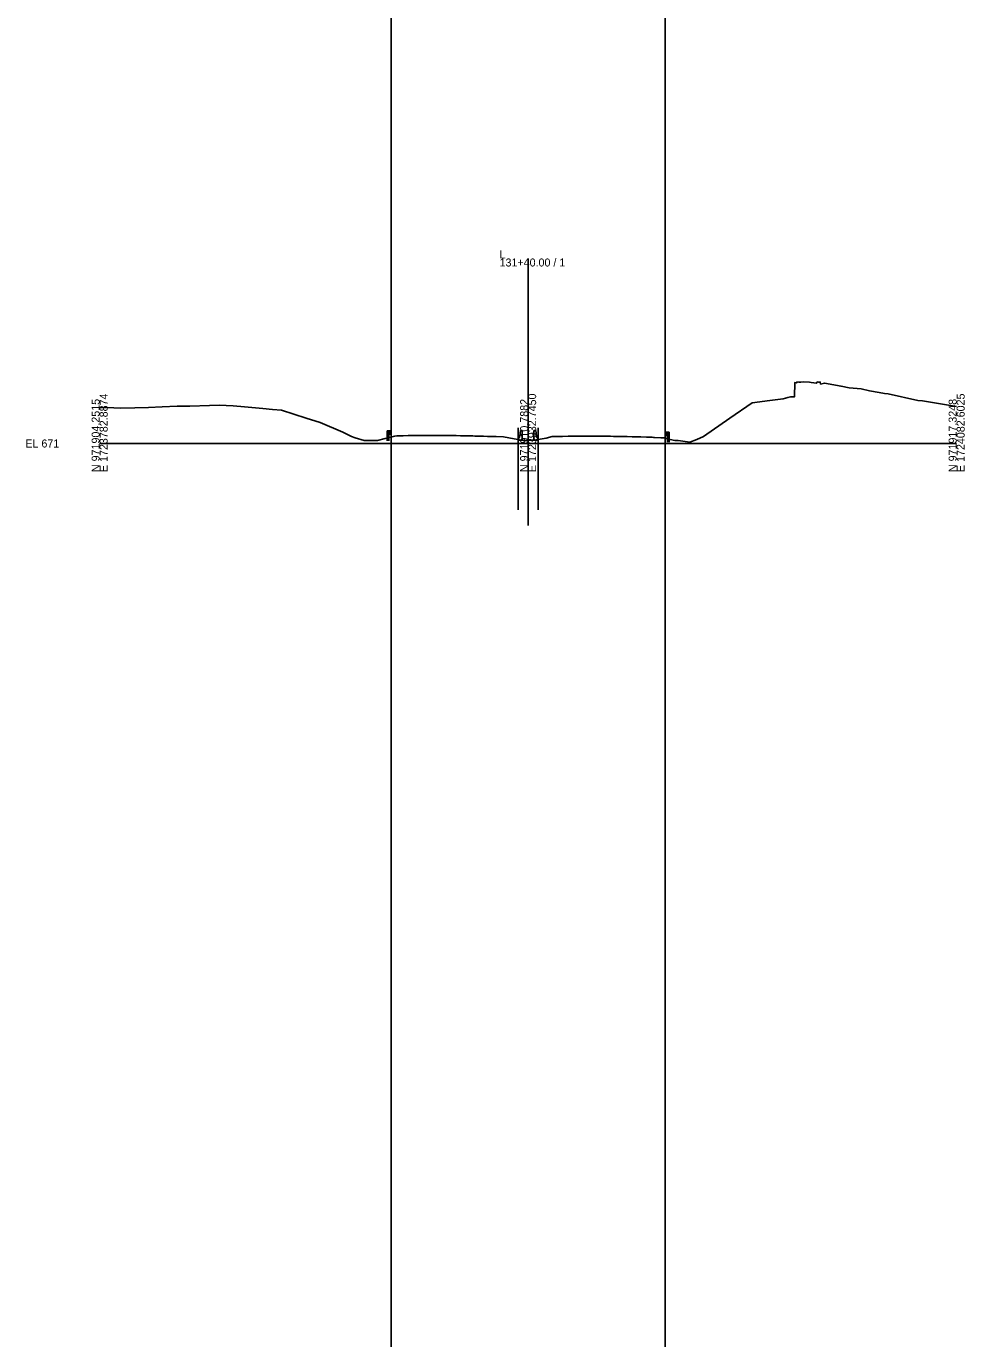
# Model space of a CAD drawing. Extents: x -26 to 303, y -29 to 15026.
# Drawn here: x -25.7 to 302.8, y 3186.7 to 3646 of the extents above; entities that cross this region are included whole.
import ezdxf

# ---------------------------------------------------------------- set-up
doc = ezdxf.new("R2010")
doc.units = 0
for name, color, linetype in [('Exist Cross Section Cell', 7, 'Continuous'), ('Exist XS Center Line Elevation Label', 7, 'Continuous'), ('Exist XS Ground Line', 7, 'Continuous'), ('Scratch_Level_0', 7, 'Continuous'), ('Typical Guardrail CELL', 7, 'Continuous'), ('Typical Median Barrier CELL', 7, 'Continuous')]:
    doc.layers.add(name, color=color, linetype=linetype)

msp = doc.modelspace()

# ---------------------------------------------------------------- linework, layer by layer
at = {"layer": 'Exist Cross Section Cell'}
for p, q in [((150, 3500), (150, 3564.75)), ((0, 3500), (150, 3500)), ((150, 3500), (300, 3500))]:
    msp.add_line(p, q, dxfattribs=at)
at = {"layer": 'Exist XS Ground Line'}
msp.add_lwpolyline([(0, 3512.47), (2.76, 3512.56), (7.13, 3512.35), (12.35, 3512.48), (17.14, 3512.62), (21.94, 3512.84), (27.15, 3513.02), (31.53, 3513.05), (38.49, 3513.29), (41.82, 3513.42), (46.79, 3513.24), (50.71, 3512.89), (57.18, 3512.21), (60.47, 3511.94), (63.63, 3511.7), (72.33, 3508.81), (77.2, 3507.34), (85.16, 3504), (88.22, 3502.47), (89.47, 3502.04), (92.6, 3501.04), (97.26, 3501), (99.96, 3501.7), (102.81, 3502.47), (103.32, 3502.6), (103.98, 3502.65), (104.6, 3502.67), (106.29, 3502.73), (107.97, 3502.77), (108.81, 3502.8), (110.21, 3502.81), (111.19, 3502.82), (112.09, 3502.82), (113.83, 3502.81), (115.2, 3502.82), (116.33, 3502.83), (117.54, 3502.82), (118.82, 3502.82), (120.16, 3502.81), (121.32, 3502.8), (122.33, 3502.8), (123.04, 3502.8), (123.41, 3502.79), (123.81, 3502.79), (124.76, 3502.76), (126.31, 3502.72), (127.16, 3502.7), (128.81, 3502.67), (130.61, 3502.63), (131.33, 3502.61), (133.26, 3502.56), (133.84, 3502.54), (134.41, 3502.52), (135.76, 3502.48), (136.35, 3502.46), (138.54, 3502.41), (138.86, 3502.4), (141.36, 3502.35), (148.21, 3501.06), (150.16, 3501.04), (152.09, 3501.12), (156.3, 3501.87), (158.4, 3502.42), (159.07, 3502.44), (159.63, 3502.45), (161.37, 3502.48), (162.03, 3502.49), (164.05, 3502.51), (164.49, 3502.52), (165.63, 3502.53), (166.37, 3502.53), (167.26, 3502.54), (168.87, 3502.55), (170.35, 3502.56), (171.39, 3502.57), (172.51, 3502.56), (173.89, 3502.57), (175.14, 3502.56), (176.4, 3502.56), (177.29, 3502.55), (177.73, 3502.54), (178.87, 3502.52), (179.92, 3502.5), (181.38, 3502.47), (182.95, 3502.44), (183.86, 3502.42), (184.7, 3502.4), (186.37, 3502.37), (188.19, 3502.33), (188.86, 3502.32), (189.48, 3502.3), (191.39, 3502.23), (193.47, 3502.16), (193.89, 3502.15), (194.28, 3502.13), (196.41, 3502.04), (197.25, 3502.03), (197.89, 3502.02), (198.05, 3501.84), (198.35, 3501.77), (199.72, 3501.35), (201.31, 3501.1), (202.52, 3501.1), (206.59, 3500.52), (209.09, 3501.41), (211.37, 3502.44), (220.63, 3508.92), (228.37, 3514.27), (234.56, 3515.03), (239.24, 3515.62), (240.94, 3516.12), (241.83, 3516.32), (241.93, 3516.32), (242.41, 3516.32), (243.21, 3516.3), (243.35, 3521.31), (244, 3521.2), (244.06, 3521.53), (244.73, 3521.48), (245.15, 3521.5), (245.43, 3521.43), (246.37, 3521.58), (248.44, 3521.45), (249.12, 3521.33), (250.99, 3521.1), (251.21, 3521.55), (251.62, 3521.52), (252.24, 3521.52), (252.36, 3520.8), (253.75, 3521.13), (259.57, 3520.02), (262.32, 3519.53), (266.54, 3519.08), (269.48, 3518.48), (272.93, 3517.81), (274.7, 3517.54), (276.07, 3517.35), (286.41, 3515.09), (287.99, 3514.9), (300, 3512.93)], dxfattribs=at)
at = {"layer": 'Scratch_Level_0'}
for p, q in [((102, 15009.56), (102, -28.7)), ((198, 15009.56), (198, -28.7)), ((146.46, 3505.5), (146.46, 3476.8)), ((153.54, 3505.5), (153.54, 3476.8)), ((150, 3500), (150, 3471.3)), ((150, 3500), (150, 3471.3))]:
    msp.add_line(p, q, dxfattribs=at)
at = {"layer": 'Typical Guardrail CELL'}
for p, q in [((101.18, 3504.38), (100.68, 3504.38)), ((100.68, 3504.38), (100.68, 3501.9)), ((101.18, 3501.9), (100.68, 3501.9)), ((100.68, 3501.9), (100.68, 3500.89)), ((101.18, 3504.38), (101.18, 3501.9)), ((101.18, 3504.38), (101.68, 3504.38)), ((101.18, 3503.22), (101.68, 3503.22)), ((101.18, 3501.9), (101.18, 3500.89)), ((101.68, 3504.38), (101.68, 3503.22)), ((101.68, 3504.38), (101.97, 3504.18)), ((101.68, 3503.85), (101.97, 3504.05)), ((101.68, 3503.8), (101.68, 3503.85)), ((101.68, 3503.8), (101.68, 3503.75)), ((101.68, 3503.75), (101.97, 3503.55)), ((101.68, 3503.22), (101.97, 3503.42)), ((198.32, 3503.96), (198.03, 3503.76)), ((198.32, 3503.42), (198.03, 3503.63)), ((198.32, 3503.33), (198.03, 3503.13)), ((198.32, 3502.8), (198.03, 3503)), ((198.82, 3503.96), (198.32, 3503.96)), ((198.32, 3503.96), (198.32, 3502.8)), ((198.32, 3503.38), (198.32, 3503.42)), ((198.32, 3503.38), (198.32, 3503.33)), ((198.82, 3502.8), (198.32, 3502.8)), ((198.82, 3503.96), (198.82, 3501.47)), ((198.82, 3503.96), (199.32, 3503.96)), ((198.82, 3501.47), (199.32, 3501.47)), ((198.82, 3501.47), (198.82, 3500.46)), ((199.32, 3503.96), (199.32, 3501.47)), ((199.32, 3501.47), (199.32, 3500.46))]:
    msp.add_line(p, q, dxfattribs=at)
for centre, start, end in [((101.92, 3504.11), 304.9888, 54.997), ((101.92, 3503.49), 304.9634, 54.9941), ((198.08, 3503.69), 125.003, 235.0112), ((198.08, 3503.06), 125.0059, 235.0366)]:
    msp.add_arc(centre, 0.0776, start, end, dxfattribs=at)
at = {"layer": 'Typical Median Barrier CELL'}
for p, q in [((146.46, 3501.6), (146.92, 3502.26)), ((146.46, 3501.19), (146.46, 3501.6)), ((147.96, 3501.19), (146.46, 3501.19)), ((147.07, 3502.65), (147.29, 3504.6)), ((147.29, 3504.6), (147.96, 3504.6)), ((147.96, 3504.6), (147.96, 3501.19)), ((152.71, 3504.6), (152.04, 3504.6)), ((152.04, 3504.6), (152.04, 3501.19)), ((152.04, 3501.19), (153.54, 3501.19)), ((152.93, 3502.65), (152.71, 3504.6)), ((153.54, 3501.6), (153.08, 3502.26)), ((153.54, 3501.19), (153.54, 3501.6))]:
    msp.add_line(p, q, dxfattribs=at)
for centre, start, end in [((146.24, 3502.74), 325.0039, 353.9447), ((153.76, 3502.74), 186.0553, 214.9961)]:
    msp.add_arc(centre, 0.833, start, end, dxfattribs=at)

# ---------------------------------------------------------------- texts
at = {"layer": 'Exist Cross Section Cell'}
for s, p in [('131+40.00 / 1', (140, 3561.95)), ('L', (140, 3564.75)), ('EL 671', (-26, 3498.6))]:
    msp.add_text(s, height=2.8, dxfattribs=at).set_placement(p)
for s, p in [('N 971904.2515', (0, 3490)), ('E 1723782.8874', (2.8, 3490)), ('N 971910.7882', (150, 3490)), ('E 1723932.7450', (152.8, 3490)), ('N 971917.3248', (300, 3490)), ('E 1724082.6025', (302.8, 3490))]:
    msp.add_text(s, height=2.8, rotation=90, dxfattribs=at).set_placement(p)
at = {"layer": 'Exist XS Center Line Elevation Label'}
msp.add_text('672.04', height=0.18, dxfattribs=at).set_placement((149.61, 3500.55))

doc.saveas('drawing.dxf')
